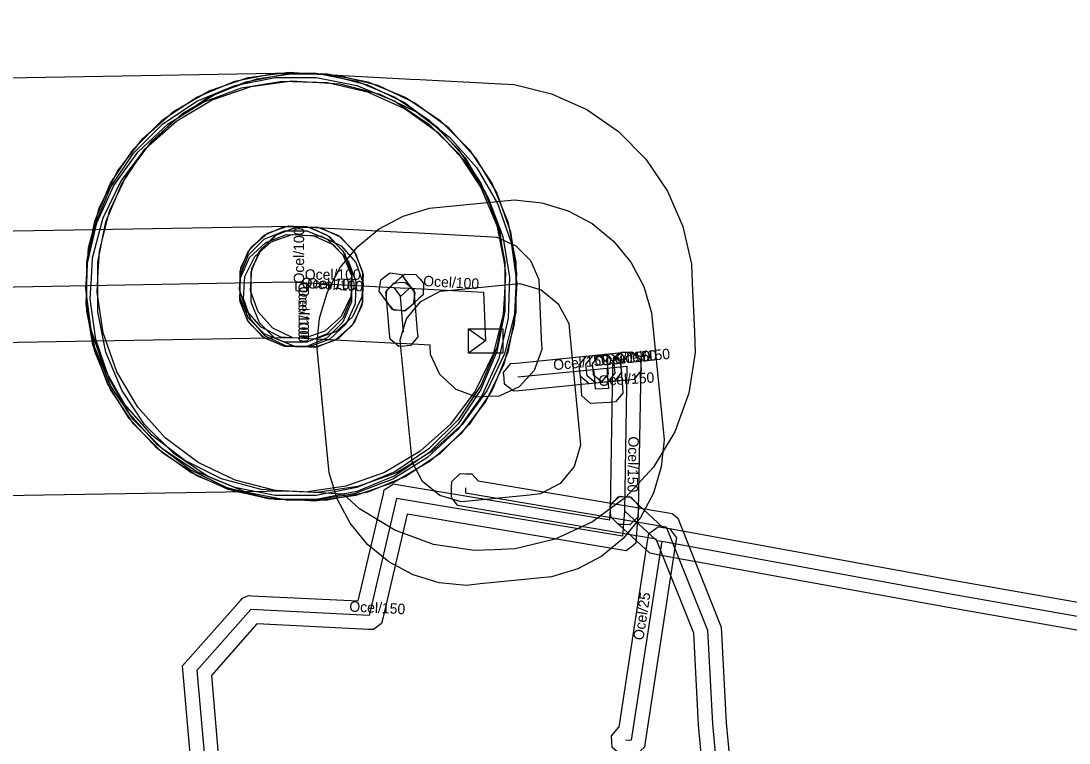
# Model space of a CAD drawing. Extents: x -569373 to -565022, y -1135090 to -1131496.
# Drawn here: x -565666.6 to -565591.3, y -1133269.9 to -1133218.1 of the extents above; entities that cross this region are included whole.
import ezdxf

# ---------------------------------------------------------------- set-up
doc = ezdxf.new("R2010")
doc.units = 0
for name, color, linetype in [('1', 7, 'Continuous'), ('24', 7, 'Continuous'), ('3', 7, 'Continuous'), ('30', 7, 'Continuous'), ('31', 7, 'Continuous'), ('34', 7, 'Continuous'), ('38', 7, 'Continuous'), ('40', 7, 'Continuous'), ('55', 7, 'Continuous'), ('56', 7, 'Continuous'), ('7', 7, 'Continuous'), ('8', 7, 'Continuous')]:
    doc.layers.add(name, color=color, linetype=linetype)

# ---------------------------------------------------------------- blocks, each defined once
blk = doc.blocks.new('REG_VTL')
at = {"layer": '31'}
for p, q in [((-1.225, 0.866), (1.225, 0.866)), ((1.225, 0.866), (1.225, -0.866)), ((1.225, -0.866), (-1.225, -0.866))]:
    blk.add_line(p, q, dxfattribs=at)
blk.add_lwpolyline([(-1.225, 0.866), (0, 0), (-1.225, -0.866)], close=True, dxfattribs=at)

msp = doc.modelspace()

# ---------------------------------------------------------------- linework, layer by layer
at = {"layer": '1'}
for points in [[(-565668.926, -1133222.157), (-565646.922, -1133221.783), (-565646.02, -1133221.832), (-565644.545, -1133221.912), (-565641.682, -1133222.644), (-565639.017, -1133223.92), (-565636.653, -1133225.692), (-565634.679, -1133227.891), (-565633.173, -1133230.433), (-565632.191, -1133233.22), (-565631.772, -1133236.145), (-565631.852, -1133237.62), (-565631.932, -1133239.095), (-565632.664, -1133241.958), (-565633.94, -1133244.623), (-565635.712, -1133246.987), (-565637.911, -1133248.961), (-565640.453, -1133250.467), (-565643.24, -1133251.449), (-565646.165, -1133251.868), (-565647.474, -1133251.797), (-565667.794, -1133252.143)], [(-565668.511, -1133233.152), (-565647.126, -1133232.788), (-565646.614, -1133232.816), (-565645.82, -1133232.859), (-565644.384, -1133233.546), (-565643.322, -1133234.731), (-565642.793, -1133236.232), (-565642.836, -1133237.026), (-565642.879, -1133237.82), (-565643.566, -1133239.256), (-565644.751, -1133240.318), (-565646.252, -1133240.847), (-565647.046, -1133240.804), (-565647.274, -1133240.792), (-565668.209, -1133241.148)], [(-565654.314, -1133271.749), (-565654.953, -1133264.339), (-565650.799, -1133259.638), (-565650.648, -1133259.467), (-565650.229, -1133259.29), (-565650.001, -1133259.301), (-565642.343, -1133259.68), (-565640.564, -1133252.092), (-565640.474, -1133251.707), (-565639.816, -1133251.269), (-565639.426, -1133251.334), (-565624.293, -1133253.854), (-565624.237, -1133253.123), (-565624.205, -1133252.71), (-565623.576, -1133252.171), (-565623.163, -1133252.203), (-565622.75, -1133252.235), (-565622.211, -1133252.864), (-565622.243, -1133253.277), (-565622.383, -1133255.097), (-565622.417, -1133255.536), (-565622.763, -1133255.807), (-565623.11, -1133256.079), (-565623.544, -1133256.006), (-565638.83, -1133253.46), (-565640.586, -1133260.948), (-565640.669, -1133261.301), (-565641.248, -1133261.737), (-565641.609, -1133261.719), (-565649.619, -1133261.323), (-565652.887, -1133265.021), (-565652.326, -1133271.531)], [(-565515.803, -1133275.105), (-565551.745, -1133268.645), (-565600.006, -1133260.154), (-565620.74, -1133256.384), (-565621.407, -1133256.261), (-565623.919, -1133253.934), (-565624.223, -1133253.652), (-565624.255, -1133252.825), (-565623.974, -1133252.521), (-565623.692, -1133252.217), (-565622.865, -1133252.185), (-565622.561, -1133252.466), (-565620.473, -1133254.399), (-565620.38, -1133254.416), (-565599.654, -1133258.186), (-565551.395, -1133266.675), (-565515.457, -1133273.135)]]:
    msp.add_lwpolyline(points, dxfattribs=at)
for points in [[(-565646.779, -1133251.831), (-565646.799, -1133251.83), (-565647.029, -1133251.83), (-565647.813, -1133251.778), (-565647.828, -1133251.777), (-565649.302, -1133251.679), (-565652.155, -1133250.911), (-565654.804, -1133249.601), (-565657.146, -1133247.799), (-565659.092, -1133245.576), (-565660.566, -1133243.015), (-565661.513, -1133240.216), (-565661.895, -1133237.286), (-565661.797, -1133235.812), (-565661.699, -1133234.338), (-565660.931, -1133231.485), (-565659.621, -1133228.836), (-565657.819, -1133226.494), (-565655.596, -1133224.548), (-565653.035, -1133223.074), (-565650.236, -1133222.127), (-565647.306, -1133221.745), (-565645.942, -1133221.836), (-565645.281, -1133221.869), (-565643.806, -1133221.943), (-565640.94, -1133222.663), (-565638.27, -1133223.929), (-565635.898, -1133225.691), (-565633.916, -1133227.882), (-565632.399, -1133230.418), (-565631.406, -1133233.2), (-565630.975, -1133236.124), (-565631.049, -1133237.599), (-565631.123, -1133239.074), (-565631.843, -1133241.94), (-565633.109, -1133244.61), (-565634.871, -1133246.982), (-565637.062, -1133248.964), (-565639.598, -1133250.481), (-565642.38, -1133251.474), (-565645.304, -1133251.905)], [(-565631.83, -1133235.333), (-565631.83, -1133236.81), (-565631.83, -1133237.11), (-565631.83, -1133238.587), (-565632.406, -1133241.485), (-565633.537, -1133244.215), (-565635.179, -1133246.672), (-565637.268, -1133248.761), (-565639.725, -1133250.403), (-565642.455, -1133251.534), (-565645.353, -1133252.11), (-565646.83, -1133252.11), (-565648.307, -1133252.11), (-565651.205, -1133251.534), (-565653.935, -1133250.403), (-565656.392, -1133248.761), (-565658.481, -1133246.672), (-565660.123, -1133244.215), (-565661.254, -1133241.485), (-565661.83, -1133238.587), (-565661.83, -1133237.11), (-565661.83, -1133236.81), (-565661.83, -1133235.333), (-565661.254, -1133232.435), (-565660.123, -1133229.705), (-565658.481, -1133227.248), (-565656.392, -1133225.159), (-565653.935, -1133223.517), (-565651.205, -1133222.386), (-565648.307, -1133221.81), (-565646.83, -1133221.81), (-565645.353, -1133221.81), (-565642.455, -1133222.386), (-565639.725, -1133223.517), (-565637.268, -1133225.159), (-565635.179, -1133227.248), (-565633.537, -1133229.705), (-565632.406, -1133232.435)], [(-565631.83, -1133235.633), (-565631.83, -1133237.11), (-565631.83, -1133237.41), (-565631.83, -1133238.887), (-565632.406, -1133241.785), (-565633.537, -1133244.515), (-565635.179, -1133246.972), (-565637.268, -1133249.061), (-565639.725, -1133250.703), (-565642.455, -1133251.834), (-565645.353, -1133252.41), (-565646.83, -1133252.41), (-565648.307, -1133252.41), (-565651.205, -1133251.834), (-565653.935, -1133250.703), (-565656.392, -1133249.061), (-565658.481, -1133246.972), (-565660.123, -1133244.515), (-565661.254, -1133241.785), (-565661.83, -1133238.887), (-565661.83, -1133237.41), (-565661.83, -1133237.11), (-565661.83, -1133235.633), (-565661.254, -1133232.735), (-565660.123, -1133230.005), (-565658.481, -1133227.548), (-565656.392, -1133225.459), (-565653.935, -1133223.817), (-565651.205, -1133222.686), (-565648.307, -1133222.11), (-565646.83, -1133222.11), (-565645.353, -1133222.11), (-565642.455, -1133222.686), (-565639.725, -1133223.817), (-565637.268, -1133225.459), (-565635.179, -1133227.548), (-565633.537, -1133230.005), (-565632.406, -1133232.735)], [(-565642.253, -1133253.071), (-565643.406, -1133252.013), (-565646.835, -1133251.828), (-565648.31, -1133251.749), (-565651.173, -1133251.018), (-565653.838, -1133249.742), (-565656.204, -1133247.971), (-565658.178, -1133245.773), (-565659.685, -1133243.231), (-565660.667, -1133240.445), (-565661.087, -1133237.52), (-565661.008, -1133236.045), (-565660.929, -1133234.57), (-565660.198, -1133231.707), (-565658.922, -1133229.042), (-565657.151, -1133226.676), (-565654.953, -1133224.702), (-565652.411, -1133223.195), (-565649.625, -1133222.213), (-565646.7, -1133221.793), (-565645.225, -1133221.872), (-565638.988, -1133222.207), (-565638.597, -1133222.228), (-565637.926, -1133222.258), (-565632.534, -1133222.552), (-565631.151, -1133222.627), (-565628.459, -1133223.282), (-565625.932, -1133224.419), (-565623.657, -1133225.999), (-565621.709, -1133227.97), (-565620.155, -1133230.263), (-565619.047, -1133232.803), (-565618.423, -1133235.502), (-565618.364, -1133236.886), (-565618.214, -1133240.376), (-565618.151, -1133241.852), (-565618.602, -1133244.772), (-565619.615, -1133247.548), (-565621.149, -1133250.073), (-565623.147, -1133252.25), (-565625.531, -1133253.995), (-565628.209, -1133255.242), (-565631.08, -1133255.943), (-565632.556, -1133256.006), (-565634.032, -1133256.069), (-565636.952, -1133255.618), (-565639.728, -1133254.605)], [(-565661.03, -1133238.927), (-565661.03, -1133237.45), (-565661.03, -1133236.85), (-565661.03, -1133235.373), (-565660.454, -1133232.475), (-565659.323, -1133229.745), (-565657.681, -1133227.288), (-565655.592, -1133225.199), (-565653.135, -1133223.557), (-565650.405, -1133222.426), (-565647.507, -1133221.85), (-565646.03, -1133221.85), (-565644.553, -1133221.85), (-565641.655, -1133222.426), (-565638.925, -1133223.557), (-565636.468, -1133225.199), (-565634.379, -1133227.288), (-565632.737, -1133229.745), (-565631.606, -1133232.475), (-565631.03, -1133235.373), (-565631.03, -1133236.85), (-565631.03, -1133237.45), (-565631.03, -1133238.927), (-565631.606, -1133241.825), (-565632.737, -1133244.555), (-565634.379, -1133247.012), (-565636.468, -1133249.101), (-565638.925, -1133250.743), (-565641.655, -1133251.874), (-565644.553, -1133252.45), (-565646.03, -1133252.45), (-565647.507, -1133252.45), (-565650.405, -1133251.874), (-565653.135, -1133250.743), (-565655.592, -1133249.101), (-565657.681, -1133247.012), (-565659.323, -1133244.555), (-565660.454, -1133241.825)], [(-565647.807, -1133222.369), (-565646.33, -1133222.418), (-565646.03, -1133222.428), (-565644.554, -1133222.477), (-565641.676, -1133223.15), (-565638.986, -1133224.371), (-565636.585, -1133226.094), (-565634.567, -1133228.252), (-565633.008, -1133230.762), (-565631.969, -1133233.528), (-565631.489, -1133236.443), (-565631.538, -1133237.92), (-565631.587, -1133239.396), (-565632.26, -1133242.274), (-565633.481, -1133244.964), (-565635.204, -1133247.365), (-565637.362, -1133249.383), (-565639.872, -1133250.942), (-565642.638, -1133251.981), (-565645.553, -1133252.461), (-565647.03, -1133252.412), (-565647.33, -1133252.402), (-565648.806, -1133252.353), (-565651.684, -1133251.68), (-565654.374, -1133250.459), (-565656.775, -1133248.736), (-565658.793, -1133246.578), (-565660.352, -1133244.068), (-565661.391, -1133241.302), (-565661.871, -1133238.387), (-565661.822, -1133236.91), (-565661.773, -1133235.434), (-565661.1, -1133232.556), (-565659.879, -1133229.866), (-565658.156, -1133227.465), (-565655.998, -1133225.447), (-565653.488, -1133223.888), (-565650.722, -1133222.849)], [(-565647.107, -1133222.359), (-565645.632, -1133222.447), (-565645.132, -1133222.477), (-565643.657, -1133222.565), (-565640.799, -1133223.314), (-565638.142, -1133224.606), (-565635.788, -1133226.392), (-565633.827, -1133228.603), (-565632.336, -1133231.153), (-565631.37, -1133233.946), (-565630.969, -1133236.873), (-565631.057, -1133238.348), (-565631.145, -1133239.823), (-565631.894, -1133242.681), (-565633.186, -1133245.338), (-565634.972, -1133247.692), (-565637.183, -1133249.653), (-565639.733, -1133251.144), (-565642.526, -1133252.11), (-565645.453, -1133252.511), (-565646.928, -1133252.423), (-565647.428, -1133252.393), (-565648.903, -1133252.305), (-565651.761, -1133251.556), (-565654.418, -1133250.264), (-565656.772, -1133248.478), (-565658.733, -1133246.267), (-565660.224, -1133243.717), (-565661.19, -1133240.924), (-565661.591, -1133237.997), (-565661.503, -1133236.522), (-565661.415, -1133235.047), (-565660.666, -1133232.189), (-565659.374, -1133229.532), (-565657.588, -1133227.178), (-565655.377, -1133225.217), (-565652.827, -1133223.726), (-565650.034, -1133222.76)], [(-565646.549, -1133232.82), (-565646.399, -1133232.83), (-565646.33, -1133232.83), (-565645.83, -1133232.855), (-565645.035, -1133232.895), (-565643.597, -1133233.576), (-565642.53, -1133234.757), (-565641.995, -1133236.255), (-565642.035, -1133237.05), (-565642.075, -1133237.845), (-565642.756, -1133239.283), (-565643.937, -1133240.35), (-565645.435, -1133240.885), (-565646.23, -1133240.845), (-565646.53, -1133240.83), (-565646.663, -1133240.83), (-565647.081, -1133240.802), (-565647.096, -1133240.801), (-565647.89, -1133240.748), (-565649.316, -1133240.043), (-565650.364, -1133238.845), (-565650.874, -1133237.338), (-565650.821, -1133236.544), (-565650.768, -1133235.75), (-565650.063, -1133234.324), (-565648.865, -1133233.276), (-565647.358, -1133232.766), (-565646.564, -1133232.819)], [(-565647.492, -1133233.386), (-565646.697, -1133233.412), (-565646.397, -1133233.422), (-565645.602, -1133233.448), (-565644.153, -1133234.106), (-565643.065, -1133235.268), (-565642.506, -1133236.758), (-565642.532, -1133237.553), (-565642.558, -1133238.348), (-565643.216, -1133239.797), (-565644.378, -1133240.885), (-565645.868, -1133241.444), (-565646.663, -1133241.418), (-565646.963, -1133241.408), (-565647.758, -1133241.382), (-565649.207, -1133240.724), (-565650.295, -1133239.562), (-565650.854, -1133238.072), (-565650.828, -1133237.277), (-565650.802, -1133236.482), (-565650.144, -1133235.033), (-565648.982, -1133233.945)], [(-565642.83, -1133236.014), (-565642.83, -1133236.81), (-565642.83, -1133237.11), (-565642.83, -1133237.906), (-565643.439, -1133239.376), (-565644.564, -1133240.501), (-565646.034, -1133241.11), (-565646.83, -1133241.11), (-565647.626, -1133241.11), (-565649.096, -1133240.501), (-565650.221, -1133239.376), (-565650.83, -1133237.906), (-565650.83, -1133237.11), (-565650.83, -1133236.81), (-565650.83, -1133236.014), (-565650.221, -1133234.544), (-565649.096, -1133233.419), (-565647.626, -1133232.81), (-565646.83, -1133232.81), (-565646.034, -1133232.81), (-565644.564, -1133233.419), (-565643.439, -1133234.544)], [(-565642.83, -1133236.314), (-565642.83, -1133237.11), (-565642.83, -1133237.41), (-565642.83, -1133238.206), (-565643.439, -1133239.676), (-565644.564, -1133240.801), (-565646.034, -1133241.41), (-565646.83, -1133241.41), (-565647.626, -1133241.41), (-565649.096, -1133240.801), (-565650.221, -1133239.676), (-565650.83, -1133238.206), (-565650.83, -1133237.41), (-565650.83, -1133237.11), (-565650.83, -1133236.314), (-565650.221, -1133234.844), (-565649.096, -1133233.719), (-565647.626, -1133233.11), (-565646.83, -1133233.11), (-565646.034, -1133233.11), (-565644.564, -1133233.719), (-565643.439, -1133234.844)], [(-565647.084, -1133233.379), (-565646.29, -1133233.427), (-565645.79, -1133233.457), (-565644.996, -1133233.505), (-565643.565, -1133234.201), (-565642.509, -1133235.392), (-565641.989, -1133236.896), (-565642.037, -1133237.69), (-565642.085, -1133238.484), (-565642.781, -1133239.915), (-565643.972, -1133240.971), (-565645.476, -1133241.491), (-565646.27, -1133241.443), (-565646.77, -1133241.413), (-565647.564, -1133241.365), (-565648.995, -1133240.669), (-565650.051, -1133239.478), (-565650.571, -1133237.974), (-565650.523, -1133237.18), (-565650.475, -1133236.386), (-565649.779, -1133234.955), (-565648.588, -1133233.899)], [(-565637.162, -1133241.987), (-565637.19, -1133241.326), (-565638.868, -1133241.235), (-565639.538, -1133241.205), (-565640.015, -1133241.179), (-565646.245, -1133240.844), (-565647.039, -1133240.801), (-565648.475, -1133240.114), (-565649.538, -1133238.93), (-565650.067, -1133237.429), (-565650.024, -1133236.635), (-565649.981, -1133235.841), (-565649.294, -1133234.405), (-565648.11, -1133233.342), (-565646.609, -1133232.813), (-565645.815, -1133232.856), (-565639.583, -1133233.191), (-565639.142, -1133233.215), (-565638.472, -1133233.245), (-565633.132, -1133233.536), (-565632.388, -1133233.576), (-565631.029, -1133234.188), (-565629.981, -1133235.248), (-565629.386, -1133236.614), (-565629.354, -1133237.358), (-565629.204, -1133240.848), (-565629.17, -1133241.643), (-565629.715, -1133243.138), (-565630.791, -1133244.311), (-565632.233, -1133244.982), (-565633.028, -1133245.016), (-565633.823, -1133245.05), (-565635.318, -1133244.505), (-565636.491, -1133243.429)], [(-565650.03, -1133238.246), (-565650.03, -1133237.45), (-565650.03, -1133236.85), (-565650.03, -1133236.054), (-565649.421, -1133234.584), (-565648.296, -1133233.459), (-565646.826, -1133232.85), (-565646.03, -1133232.85), (-565645.234, -1133232.85), (-565643.764, -1133233.459), (-565642.639, -1133234.584), (-565642.03, -1133236.054), (-565642.03, -1133236.85), (-565642.03, -1133237.45), (-565642.03, -1133238.246), (-565642.639, -1133239.716), (-565643.764, -1133240.841), (-565645.234, -1133241.45), (-565646.03, -1133241.45), (-565646.826, -1133241.45), (-565648.296, -1133240.841), (-565649.421, -1133239.716)], [(-565631.391, -1133242.646), (-565630.979, -1133242.605), (-565625.539, -1133242.065), (-565625.127, -1133242.024), (-565624.486, -1133242.549), (-565624.445, -1133242.961), (-565624.404, -1133243.373), (-565624.929, -1133244.014), (-565625.341, -1133244.055), (-565630.781, -1133244.595), (-565631.193, -1133244.636), (-565631.834, -1133244.111), (-565631.875, -1133243.699), (-565631.916, -1133243.287)], [(-565625.149, -1133242.017), (-565625.056, -1133242.09), (-565624.985, -1133242.007), (-565624.572, -1133241.973), (-565624.159, -1133241.939), (-565623.527, -1133242.475), (-565623.493, -1133242.888), (-565623.373, -1133244.348), (-565623.339, -1133244.766), (-565623.613, -1133245.084), (-565623.888, -1133245.401), (-565624.306, -1133245.428), (-565625.246, -1133245.488), (-565625.659, -1133245.515), (-565626.281, -1133244.968), (-565626.308, -1133244.555), (-565626.356, -1133243.813), (-565626.433, -1133243.18), (-565626.483, -1133242.769), (-565625.971, -1133242.117), (-565625.56, -1133242.067)], [(-565625.947, -1133242.103), (-565625.534, -1133242.064), (-565625.059, -1133242.019), (-565624.647, -1133241.98), (-565624.008, -1133242.508), (-565623.969, -1133242.921), (-565623.93, -1133243.333), (-565624.458, -1133243.972), (-565624.871, -1133244.011), (-565625.346, -1133244.056), (-565625.758, -1133244.095), (-565626.397, -1133243.567), (-565626.436, -1133243.154), (-565626.475, -1133242.742)], [(-565625.472, -1133242.058), (-565625.059, -1133242.019), (-565624.584, -1133241.974), (-565624.172, -1133241.935), (-565623.533, -1133242.463), (-565623.494, -1133242.876), (-565623.455, -1133243.288), (-565623.983, -1133243.927), (-565624.396, -1133243.966), (-565624.871, -1133244.011), (-565625.283, -1133244.05), (-565625.922, -1133243.522), (-565625.961, -1133243.109), (-565626, -1133242.697)], [(-565625, -1133242.015), (-565624.587, -1133241.975), (-565623.157, -1133241.835), (-565622.745, -1133241.794), (-565622.105, -1133242.32), (-565622.065, -1133242.733), (-565622.024, -1133243.145), (-565622.55, -1133243.785), (-565622.963, -1133243.825), (-565624.393, -1133243.965), (-565624.805, -1133244.006), (-565625.445, -1133243.48), (-565625.485, -1133243.067), (-565625.526, -1133242.655)], [(-565622.053, -1133242.433), (-565622.06, -1133242.847), (-565622.24, -1133253.217), (-565622.247, -1133253.631), (-565622.843, -1133254.207), (-565623.257, -1133254.2), (-565623.671, -1133254.193), (-565624.247, -1133253.597), (-565624.24, -1133253.183), (-565624.06, -1133242.813), (-565624.053, -1133242.399), (-565623.457, -1133241.823), (-565623.043, -1133241.83), (-565622.629, -1133241.837)], [(-565623.628, -1133268.734), (-565623.609, -1133268.733), (-565621.549, -1133255.249), (-565621.486, -1133254.839), (-565620.819, -1133254.348), (-565620.409, -1133254.411), (-565619.999, -1133254.474), (-565619.508, -1133255.141), (-565619.571, -1133255.551), (-565621.751, -1133269.821), (-565621.804, -1133270.166), (-565622.317, -1133270.641), (-565622.665, -1133270.667), (-565623.065, -1133270.697), (-565623.478, -1133270.728), (-565624.106, -1133270.188), (-565624.137, -1133269.775), (-565624.168, -1133269.362)]]:
    msp.add_lwpolyline(points, close=True, dxfattribs=at)
at = {"layer": '24'}
for points in [[(-565630.88, -1133243.6), (-565625.44, -1133243.06)], [(-565624.49, -1133242.97), (-565624.37, -1133244.43), (-565625.31, -1133244.49), (-565625.36, -1133243.72), (-565625.44, -1133243.06)], [(-565625.44, -1133243.06), (-565624.965, -1133243.015)], [(-565624.965, -1133243.015), (-565624.49, -1133242.97)], [(-565624.49, -1133242.97), (-565623.06, -1133242.83)], [(-565623.06, -1133242.83), (-565623.24, -1133253.2)], [(-565623.24, -1133253.2), (-565623.38, -1133255.02), (-565639.59, -1133252.32), (-565641.56, -1133260.72), (-565650.05, -1133260.3), (-565653.92, -1133264.68), (-565653.32, -1133271.64), (-565652.17, -1133280.3)], [(-565623.24, -1133253.2), (-565620.94, -1133255.33), (-565620.56, -1133255.4), (-565599.83, -1133259.17), (-565551.57, -1133267.66), (-565515.63, -1133274.12), (-565464.19, -1133282.9), (-565463.51, -1133290.98)], [(-565620.56, -1133255.4), (-565622.74, -1133269.67), (-565623.14, -1133269.7)]]:
    msp.add_lwpolyline(points, dxfattribs=at)
at = {"layer": '3'}
for points in [[(-565637.218, -1133231.488), (-565636.236, -1133231.394), (-565632.097, -1133230.996), (-565631.118, -1133230.902), (-565629.16, -1133231.099), (-565627.278, -1133231.673), (-565625.544, -1133232.604), (-565624.025, -1133233.854), (-565622.779, -1133235.377), (-565621.853, -1133237.113), (-565621.284, -1133238.997), (-565621.188, -1133239.976), (-565620.488, -1133247.126), (-565620.392, -1133248.105), (-565620.586, -1133250.064), (-565621.158, -1133251.947), (-565622.085, -1133253.683), (-565623.334, -1133255.204), (-565624.855, -1133256.453), (-565626.59, -1133257.381), (-565628.473, -1133257.954), (-565629.452, -1133258.051), (-565633.582, -1133258.461), (-565634.562, -1133258.558), (-565636.523, -1133258.367), (-565638.409, -1133257.796), (-565640.147, -1133256.868), (-565640.909, -1133256.244), (-565641.671, -1133255.62), (-565642.922, -1133254.097), (-565643.851, -1133252.36), (-565644.424, -1133250.475), (-565644.521, -1133249.495), (-565645.23, -1133242.333), (-565645.327, -1133241.351), (-565645.134, -1133239.387), (-565644.561, -1133237.499), (-565643.63, -1133235.759), (-565643.003, -1133234.997), (-565642.376, -1133234.235), (-565640.849, -1133232.985), (-565639.108, -1133232.057)], [(-565636.455, -1133237.442), (-565635.662, -1133237.366), (-565631.523, -1133236.968), (-565630.732, -1133236.892), (-565629.212, -1133237.356), (-565627.984, -1133238.366), (-565627.236, -1133239.769), (-565627.159, -1133240.56), (-565626.459, -1133247.71), (-565626.382, -1133248.501), (-565626.844, -1133250.023), (-565627.852, -1133251.252), (-565629.254, -1133252.002), (-565630.045, -1133252.08), (-565634.175, -1133252.49), (-565634.967, -1133252.569), (-565636.49, -1133252.108), (-565637.106, -1133251.604), (-565637.721, -1133251.099), (-565638.472, -1133249.696), (-565638.551, -1133248.904), (-565639.26, -1133241.742), (-565639.338, -1133240.949), (-565638.875, -1133239.424), (-565638.369, -1133238.808), (-565637.862, -1133238.192)]]:
    msp.add_lwpolyline(points, close=True, dxfattribs=at)
at = {"layer": '34'}
for points in [[(-565592.764, -1132734.478), (-565614.33, -1132750.85), (-565672.26, -1132797.85), (-565735.74, -1132849.54), (-565758.414, -1132889.051), (-565758.428, -1132889.075), (-565763.82, -1132898.47), (-565739.86, -1132931.51), (-565719.74, -1132973.62), (-565689.16, -1133238), (-565689.16, -1133238.37), (-565670.001, -1133237.246), (-565668.36, -1133237.15), (-565647.2, -1133236.79), (-565646.83, -1133236.81)], [(-565646.83, -1133236.81), (-565646.815, -1133236.811), (-565646.53, -1133236.83), (-565646.43, -1133236.83), (-565646.03, -1133236.85)], [(-565646.03, -1133236.85), (-565639.799, -1133237.185), (-565639.34, -1133237.21), (-565638.67, -1133237.24), (-565633.35, -1133237.53), (-565633.2, -1133241.02)]]:
    msp.add_lwpolyline(points, dxfattribs=at)
at = {"layer": '38'}
for points in [[(-565646.83, -1133236.81), (-565646.83, -1133237.11)], [(-565646.83, -1133237.11), (-565646.83, -1133237.41)], [(-565646.03, -1133237.45), (-565646.03, -1133236.85)], [(-565646.83, -1133237.41), (-565646.53, -1133237.42)], [(-565646.53, -1133237.42), (-565646.03, -1133237.45)]]:
    msp.add_lwpolyline(points, dxfattribs=at)
at = {"layer": '55'}
msp.add_lwpolyline([(-565634.64, -1133251.55), (-565634.65, -1133251.91), (-565620.23, -1133254.35), (-565617.27, -1133261.77), (-565616.92, -1133268.5), (-565615.26, -1133286.34), (-565577.34, -1133290.23), (-565547.83, -1133294.34), (-565523.25, -1133295.46)], dxfattribs=at)
at = {"layer": '56'}
for points in [[(-565639.799, -1133237.185), (-565639.32, -1133237.83)], [(-565639.32, -1133237.83), (-565638.67, -1133237.24)], [(-565639.1, -1133240.39), (-565639.32, -1133237.83)]]:
    msp.add_lwpolyline(points, dxfattribs=at)
at = {"layer": '7'}
msp.add_lwpolyline([(-565616.256, -1133286.433), (-565617.918, -1133268.572), (-565618.26, -1133261.987), (-565620.951, -1133255.242), (-565634.817, -1133252.896), (-565635.186, -1133252.834), (-565635.66, -1133252.256), (-565635.65, -1133251.882), (-565635.64, -1133251.522), (-565635.628, -1133251.108), (-565635.026, -1133250.539), (-565634.612, -1133250.55), (-565634.198, -1133250.562), (-565633.736, -1133251.05), (-565620.063, -1133253.364), (-565619.805, -1133253.408), (-565619.398, -1133253.736), (-565619.301, -1133253.979), (-565616.28, -1133261.553), (-565615.922, -1133268.428), (-565614.34, -1133285.429)], dxfattribs=at)
at = {"layer": '8'}
for points in [[(-565639.243, -1133236.256), (-565638.996, -1133236.589), (-565638.517, -1133237.234), (-565638.27, -1133237.567), (-565638.391, -1133238.386), (-565638.724, -1133238.633), (-565639.057, -1133238.88), (-565639.876, -1133238.759), (-565640.123, -1133238.426), (-565640.602, -1133237.781), (-565640.849, -1133237.448), (-565640.728, -1133236.629), (-565640.395, -1133236.382), (-565640.062, -1133236.135)], [(-565640.299, -1133237.368), (-565639.992, -1133237.09), (-565639.342, -1133236.5), (-565639.035, -1133236.221), (-565638.208, -1133236.261), (-565637.93, -1133236.568), (-565637.651, -1133236.875), (-565637.691, -1133237.702), (-565637.998, -1133237.98), (-565638.648, -1133238.57), (-565638.955, -1133238.849), (-565639.782, -1133238.809), (-565640.06, -1133238.502), (-565640.339, -1133238.195)], [(-565640.061, -1133240.889), (-565640.096, -1133240.476), (-565640.316, -1133237.916), (-565640.352, -1133237.503), (-565639.819, -1133236.869), (-565639.406, -1133236.834), (-565638.993, -1133236.798), (-565638.359, -1133237.331), (-565638.324, -1133237.744), (-565638.104, -1133240.304), (-565638.068, -1133240.717), (-565638.601, -1133241.351), (-565639.014, -1133241.386), (-565639.427, -1133241.422)]]:
    msp.add_lwpolyline(points, close=True, dxfattribs=at)

# ---------------------------------------------------------------- block references
at = {"layer": '31'}
msp.add_blockref('REG_VTL', (-565633.2, -1133241.02), dxfattribs=at)

# ---------------------------------------------------------------- texts
at = {"layer": '30'}
for s, rotation, p in [('Ocel/150', 5.41187, (-565624.878, -1133242.788)), ('Ocel/150', 5.59156, (-565623.925, -1133242.695)), ('Ocel/150', 5.66888, (-565628.31, -1133243.125)), ('Ocel/150', 5.41187, (-565625.353, -1133242.833)), ('Ocel/150', 3.65222, (-565625.076, -1133244.262)), ('Ocel/150', 269.00557, (-565622.951, -1133247.865)), ('Ocel/150', 357.16789, (-565642.998, -1133260.439)), ('Ocel/25', 81.31419, (-565621.88, -1133262.533))]:
    msp.add_text(s, height=0.75, rotation=rotation, dxfattribs=at).set_placement(p)
at = {"layer": '40'}
for rotation, p in [(90, (-565646.23, -1133236.9)), (356.87982, (-565637.696, -1133237.082)), (270, (-565646.63, -1133236.81)), (270, (-565646.63, -1133237.11)), (358.09085, (-565646.43, -1133237.217)), (356.56637, (-565646.03, -1133237.238))]:
    msp.add_text('Ocel/100', height=0.75, rotation=rotation, dxfattribs=at).set_placement(p)
msp.add_text('Ocel/100', height=0.75, dxfattribs=at).set_placement((-565646.18, -1133236.63))

doc.saveas('drawing.dxf')
